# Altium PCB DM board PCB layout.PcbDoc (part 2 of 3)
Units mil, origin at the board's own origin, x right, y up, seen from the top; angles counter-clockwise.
Board outline 4444 x 6127 mil, 2 copper layers (Top Layer, Bottom Layer); 112 components, 94 nets, 2801 pads, 141 vias.
Unrouted connection lines stored in the file: 2.
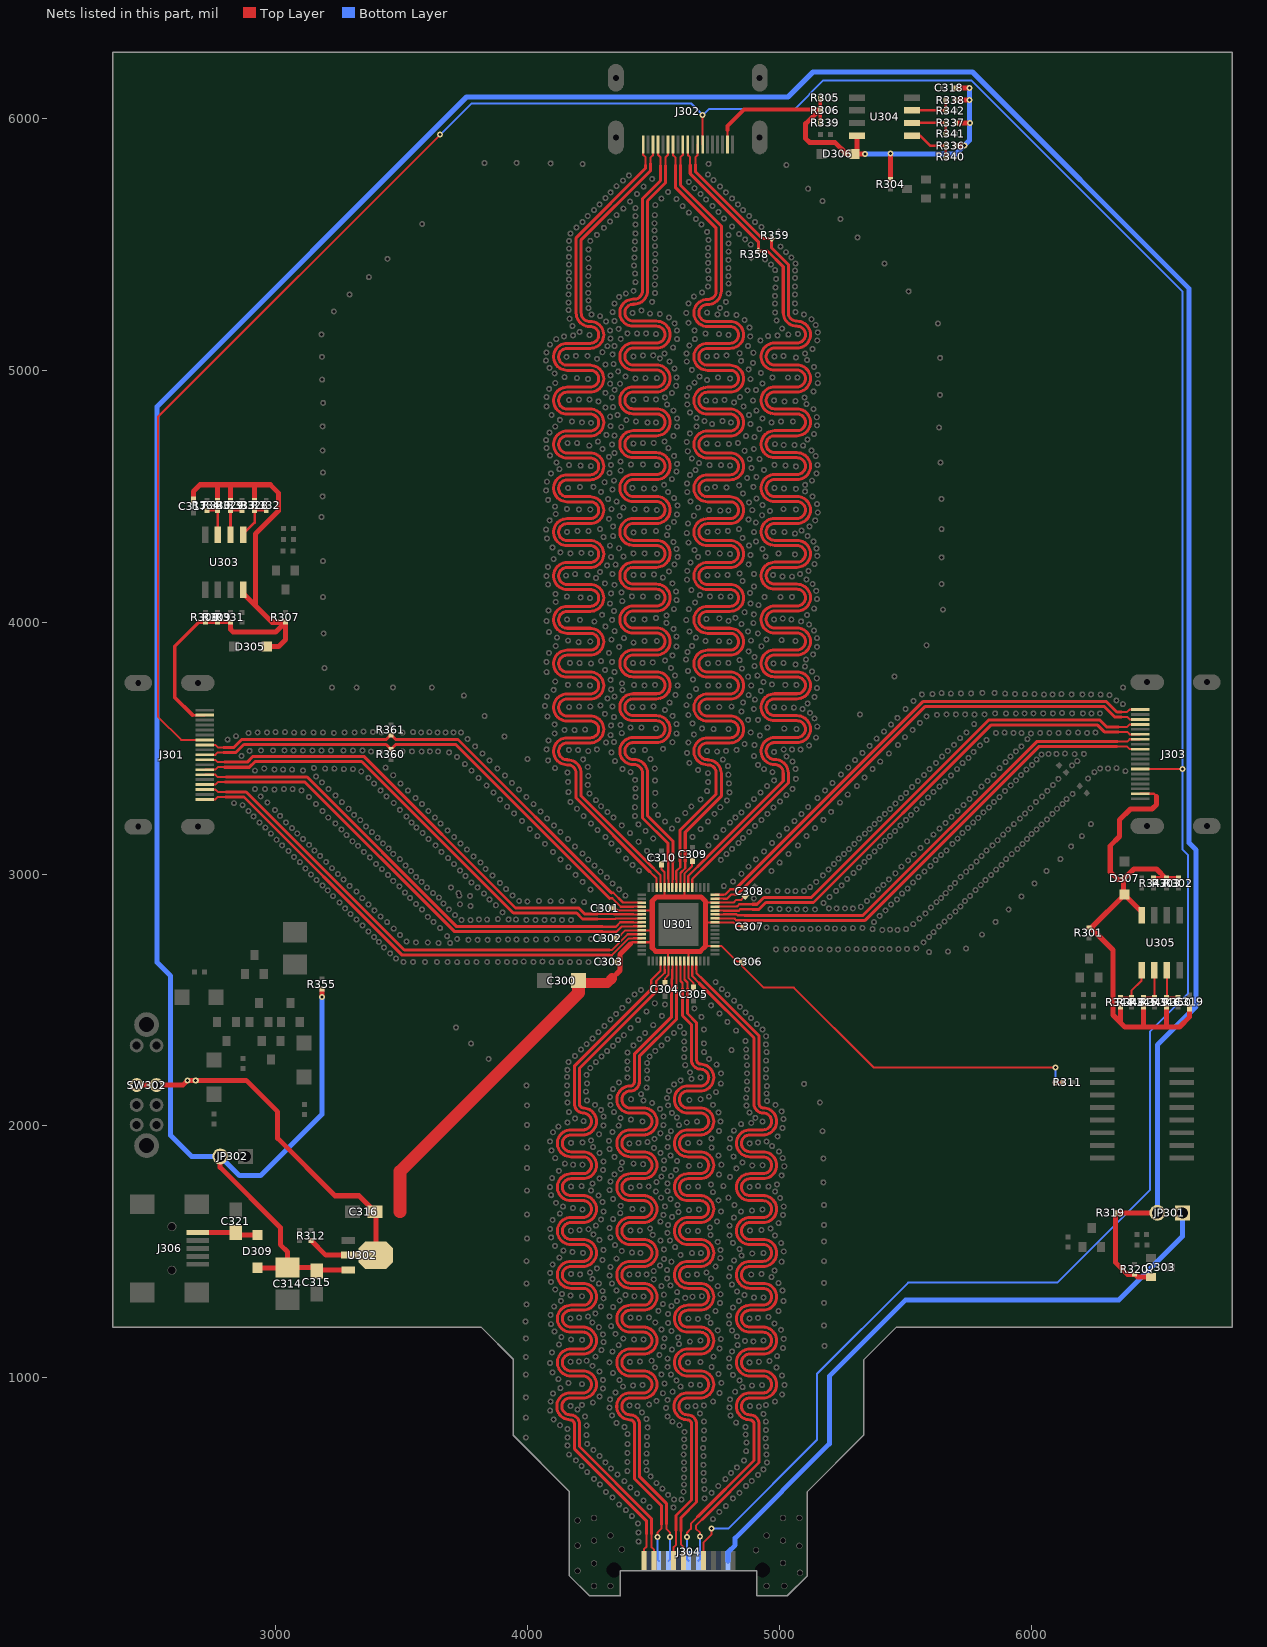
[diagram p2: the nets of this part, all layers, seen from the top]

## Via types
v1: diameter 24, hole 12, Top Layer to Bottom Layer, tented both sides, 141 vias

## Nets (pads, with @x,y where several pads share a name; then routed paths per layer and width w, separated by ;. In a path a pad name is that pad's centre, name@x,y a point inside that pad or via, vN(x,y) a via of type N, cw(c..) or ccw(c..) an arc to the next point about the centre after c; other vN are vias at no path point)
+3V3_3: C300.1 C301.1 C302.1 C303.1 C304.1 C305.1 C306.1 C307.1 C308.1 C309.1 C310.1 C316.2 R311.1 R312.2 SW302.2 SW302.6 U301.5 U301.10 U301.13 U301.22 U301.27 U301.35 U301.41 U301.46 U301.55 U301.60 U302.2 | length 6957.6
  Top Layer w7: 4544.88,2909.74 4544.88,3006
  Top Layer w8: C301.1@4335,2865 4350,2865 4359.88,2855.12 4491.87,2855.12 ; C302.1@4345,2745 4358,2745 4389.38,2776.38 4491.87,2776 ; C310.1@4533,3039 4533,3017.88 4544.88,3006 ; C304.1@4546,2570 4546,2585 4560.63,2599.63 4559,2693 ; 4623.62,2909.62 4623.62,3000.53 4653,3029.91 C309.1@4653,3053 ; 4639.37,2692.63 4639.37,2587.63 4659,2568 C305.1@4659,2548 ; C309.1@4653,3055 C309.1@4656,3058 ; 4707.39,2713.39 4771.61,2713.39 4833,2652 C306.1@4853,2652 ; 4707.39,2807.87 4817.13,2807.87 4831.59,2793.41 4854.59,2793.41 C307.1@4858,2790 ; 4707.39,2886.61 4818.61,2886.61 4829,2897 4850,2897 C308.1@4866.32,2913.32 ; C306.1@4853,2651 4853,2634 4938,2549 5058,2549 5375,2232 v1(6097,2232) ; v1(6097,2173) R311.1@6126.31,2173
  Top Layer w10: 4409,2722 4416.13,2729.13 U301.13@4454.33,2729.13 4495.16,2729.13
  Top Layer w20: SW302.6@2449.63,2162 2633,2162 v1(2652,2181) 2884,2181 3009,2056 3009,1951 3237,1723 3332,1723 3398.65,1656.35 U302.2@3398.65,1487 ; R312.2@3142,1545.32 3200.32,1487 U302.2@3298.21,1487 ; 4337.1,2586.1 4368,2617 4368,2681 4409,2722 ; C303.1@4349,2651 4368,2651 ; 4510,2907 4496,2893 4496,2707 4510,2693 4687,2693 4707.39,2713.39 4707.39,2891.61 4689.38,2909.62 4512.62,2909.62
  Top Layer w40: C300.1@4213.5,2567 4318,2567 4337.1,2586.1
  Top Layer w50: 3495,1659 3495,1820 4203.5,2528.5 C300.1@4203.5,2577
  Bottom Layer w8: v1(6097,2173) v1(6097,2232)
  Bottom Layer w20: v1(2652,2181) v1(2684,2181)
+5V_3: C314.1 C315.2 D309.2 JP301.2 JP302.2 Q303.2 R319.1 R320.2 R355.2 U302.3 | length 14380.5
  Top Layer w20: JP302.2@2781,1879 2781,1836 3020,1597 3020,1529 3049,1500 C314.1@3049,1438 ; D309.2@2930,1437 3048,1437 C314.1@3049,1438 ; v1(3185,2512) R355.2@3185,2543.32 ; U302.3@3289.37,1427.94 3168.94,1427.94 C315.2@3165,1424 3151,1438 C314.1@3049,1438 ; Q303.2@6476,1401 6421.31,1401 R320.2@6411,1411.32 6381.69,1411.32 6335.69,1457.32 R319.1@6335.69,1655 JP301.2@6501,1655
  Bottom Layer w20: v1(3185,2512) 3185,2046 2942,1803 2857,1803 JP302.2@2781,1879 2668,1879 2584,1963 2584,2596 2531,2649 2531,4856 3759,6084 5035,6084 5134,6183 5767,6183 6627,5323 6627,3123 6654,3096 6654,2474 6501,2321 JP301.2@6501,1655 JP301.2@6511,1655
+5V_A3: C317.1 D305.1 J301.18 R307.2 R308.1 R309.1 R328.1 R329.1 R330.1 R331.1 U303.8 | length 2328.9
  Top Layer w10: 2671.35,3630.65 J301.18@2720,3630.65
  Top Layer w15: 2671.35,3630.65 2601,3701 2601,3904 2696.32,3999.32 R331.1@2822,3999.32
  Top Layer w20: C317.1@2675,4485 2675,4519 2701,4545 2980,4545 3012,4513 3012,4441 2921.48,4350.48 2921.48,4065.11 ; R330.1@2770,4482.69 2770,4544 ; R331.1@2822,3999.32 2822,3971 2833,3960 3000.68,3960 R307.2@3040,3999.32 ; R329.1@2822,4482.69 2822,4545 ; U303.8@2872,4128.75 2872,4114 2986.68,3999.32 R307.2@3040,3999.32 ; R328.1@2918,4482.69 2918,4544 ; D305.1@2966,3903 3013,3903 3040,3930 R307.2@3040,3999.32
+5V_B3: C318.1 D306.1 J302.18 R304.2 R305.1 R306.1 R336.1 R337.1 R338.1 R339.1 U304.8 | length 1992.3
  Top Layer w9: J302.18@4794.65,5896 4794.65,5952
  Top Layer w15: 4794.65,5952 4794.65,5968.65 4860,6034 5162.31,6034 R306.1@5163.31,6033 ; R339.1@5163.31,5981 R305.1@5163.31,6081
  Top Layer w20: R306.1@5161,6034 5105,5978 5105,5919 5120,5904 5221,5904 5267,5858 v1(5341,5858) ; D306.1@5298,5858 5308.75,5868.75 U304.8@5308.75,5931 ; R304.2@5442,5757.69 v1(5442,5859) ; C318.1@5700,6120 v1(5755,6120) ; R336.1@5700.69,5891 v1(5735,5891) ; R337.1@5700.69,5981 v1(5757,5981) ; R338.1@5700.69,6072 v1(5756,6072)
  Bottom Layer w20: v1(5341,5858) 5701,5858 5755,5912 v1(5755,6120)
+5V_C3: C319.1 D307.1 J303.18 R301.2 R302.1 R303.1 R344.1 R345.1 R346.1 R347.1 U305.8 | length 2192
  Top Layer w9: J303.18@6433,3318.35 6487.65,3318.35 6498,3308
  Top Layer w15: R347.1@6485.31,2983.68 R302.1@6585,2983.68 ; 6552,2984.68 6553,2983.68
  Top Layer w20: R301.2@6229,2785.68 R301.2@6237.68,2785.68 ; 6354,2411 R344.1@6354,2471.32 ; D307.1@6371,2919 R301.2@6237.68,2785.68 ; U305.8@6442,2846.25 6370.13,2918.13 6366.63,2921.63 6366.63,2978.63 ; 6446,2396 R345.1@6446,2471.32 ; 6498,3308 6498,3276 6480,3258 6394,3258 6351,3215 6351,3149 6314,3112 6314,3008 6343.37,2978.63 6366.63,2978.63 ; R303.1@6534,2983.68 6497.69,3020 6408,3020 6366.63,2978.63 ; 6538,2393 R346.1@6538,2471.32 ; C319.1@6629,2467 6629,2433 6589,2393 6372,2393 6325,2440 6325,2698.37 R301.2@6237.68,2785.68
+5V_D3: J304.18 JP301.1 | length 2624.2
  Bottom Layer w20: J304.18@4797.48,274 4797.48,308.48 4825,336 4825,364 5199,738 5199,1007 5502,1310 6349,1310 6601,1562 JP301.1@6601,1655
+5V_JACK_3: 
+5V_USB_3: C321.1 D309.1 J306.1 | length 242.1
  Top Layer w20: J306.1@2692.06,1576.99 C321.1@2843,1577 2852.98,1567 D309.1@2930,1567
A0_A3: R328.2 R332.1 U303.1 | length 161.1
  Top Layer w10: U303.1@2872,4347.25 2872,4349 2918,4395 R328.2@2918,4443.31 R332.1@2964,4443.32
A0_B3: R336.2 R340.1 U304.1 | length 194.6
  Top Layer w10: U304.1@5527.25,5931 5559,5931 5599,5891 R336.2@5661.31,5891 R340.1@5661.31,5847
A0_C3: R344.2 R348.1 U305.1 | length 176.9
  Top Layer w8: R344.2@6354,2510.68 R348.1@6398,2510.68 6398,2537 6438,2577 U305.1@6438,2627
A1_A3: R329.2 R333.1 U303.2 | length 141.1
  Top Layer w10: U303.2@2822,4347.25 R329.2@2822,4443.31 R333.1@2867,4443.31
A1_B3: R337.2 R341.1 U304.2 | length 177.1
  Top Layer w10: U304.2@5527.25,5981 R337.2@5661.31,5981 R341.1@5661.31,5938
A1_C3: R345.2 R349.1 U305.2 | length 149.5
  Top Layer w8: R345.2@6446,2510.68 6488,2510.68 6489,2511.68 U305.2@6489,2617.75
A2_A3: R330.2 R334.1 U303.3 | length 138.9
  Top Layer w10: R334.1@2728,4443.31 R330.2@2770,4443.31 2772,4441.31 U303.3@2772,4347.25
A2_B3: R338.2 R342.1 U304.3 | length 174.5
  Top Layer w10: U304.3@5527.25,6031 5660.31,6031 5661.31,6032 R338.2@5661.31,6072
A2_C3: R346.2 R350.1 U305.3 | length 149.5
  Top Layer w8: U305.3@6539,2617.75 6539,2511.68 6540,2510.68 R350.1@6582,2510.68
CEC_D3: J301.13 J302.13 J303.13 J304.13 | length 12936.1
  Top Layer w8: J301.13@2720,3532.22 2625.78,3532.22 2535,3623 2535,4816 v1(3653.77,5934.77) ; J302.13@4696.22,5896 v1(4696.22,6012.78) ; J304.13@4699.06,274 4699.06,346.06 4732,379 v1(4732,402) ; J303.13@6433,3416.78 v1@6600,3416.78
  Bottom Layer w8: v1@3654.27,5934.27 3779,6059 4650,6059 v1(4696.22,6012.78) ; v1@4690.05,6018.95 4703.95,6018.95 4721,6036 5061,6036 5175,6150 5763,6150 6600,5313 6600,3098 6623,3075 6623,2526 6471,2374 6471,1745 6104,1378 5512,1378 5150,1016 5150,754 4798,402 v1(4732,402)
  other v1: 6600,3416
D0+: J304.7 U301.25 | length 3996.1
  Top Layer w8: J304.7@4580.94,280 4580.94,328.37 4590.63,338.06 4590.63,395
  Top Layer w9: U301.25@4607.87,2654.33 4607.87,2575.13 4616,2567 4616,2545
  Top Layer w12: J304.7@4580.94,274 J304.7@4580.94,280 ; 4590.63,395 4590.63,453.91 4652,515.28 4652,817 ccw(c4635.5,817) 4635.5,833.5 cw(c4635.5,887) 4582,887 cw(c4635.5,887) 4635.5,940.5 4686.77,940.5 ccw(c4686.77,974) 4720.27,974 ccw(c4686.77,974) 4686.77,1007.5 4637.23,1007.5 cw(c4637.23,1061) 4583.73,1061 cw(c4637.23,1061) 4637.23,1114.5 4686.77,1114.5 ccw(c4686.77,1148) 4720.27,1148 ccw(c4686.77,1148) 4686.77,1181.5 4637.23,1181.5 cw(c4637.23,1235) 4583.73,1235 cw(c4637.23,1235) 4637.23,1288.5 4686.77,1288.5 ccw(c4686.77,1322) 4720.27,1322 ccw(c4686.77,1322) 4686.77,1355.5 4637.23,1355.5 cw(c4637.23,1409) 4583.73,1409 cw(c4637.23,1409) 4637.23,1462.5 4686.77,1462.5 ccw(c4686.77,1496) 4720.27,1496 ccw(c4686.77,1496) 4686.77,1529.5 4637.23,1529.5 cw(c4637.23,1583) 4583.73,1583 cw(c4637.23,1583) 4637.23,1636.5 4686.77,1636.5 ccw(c4686.77,1670) 4720.27,1670 ccw(c4686.77,1670) 4686.77,1703.5 4637.23,1703.5 cw(c4637.23,1757) 4583.73,1757 cw(c4637.23,1757) 4637.23,1810.5 4686.77,1810.5 ccw(c4686.77,1844) 4720.27,1844 ccw(c4686.77,1844) 4686.77,1877.5 4637.23,1877.5 cw(c4637.23,1931) 4583.73,1931 cw(c4637.23,1931) 4637.23,1984.5 4686.77,1984.5 ccw(c4686.77,2018) 4720.27,2018 ccw(c4686.77,2018) 4686.77,2051.5 4637.23,2051.5 cw(c4637.23,2105) 4583.73,2105 cw(c4637.23,2105) 4637.23,2158.5 4686.77,2158.5 ccw(c4686.77,2192) 4720.27,2192 ccw(c4686.77,2192) 4686.77,2225.5 cw(c4686.77,2235.5) 4684.89,2225.68 cw(c4688.5,2262) 4652,2262 4652,2401.72 4616,2437.72 4616,2545
D0-: J304.9 U301.26 | length 3997.8
  Top Layer w8: 4610.63,392 4610.63,338.06 4620.31,328.37 J304.9@4620.31,290
  Top Layer w9: U301.26@4623.62,2654.33 4623.62,2581.65 4636,2569.27 4636,2545
  Top Layer w12: 4610.63,392 4610.63,445.63 4672,507 4672,817 ccw(c4635.5,817) 4635.5,853.5 cw(c4635.5,887) 4602,887 cw(c4635.5,887) 4635.5,920.5 4686.77,920.5 ccw(c4686.77,974) 4740.27,974 ccw(c4686.77,974) 4686.77,1027.5 4637.23,1027.5 cw(c4637.23,1061) 4603.73,1061 cw(c4637.23,1061) 4637.23,1094.5 4686.77,1094.5 ccw(c4686.77,1148) 4740.27,1148 ccw(c4686.77,1148) 4686.77,1201.5 4637.23,1201.5 cw(c4637.23,1235) 4603.73,1235 cw(c4637.23,1235) 4637.23,1268.5 4686.77,1268.5 ccw(c4686.77,1322) 4740.27,1322 ccw(c4686.77,1322) 4686.77,1375.5 4637.23,1375.5 cw(c4637.23,1409) 4603.73,1409 cw(c4637.23,1409) 4637.23,1442.5 4686.77,1442.5 ccw(c4686.77,1496) 4740.27,1496 ccw(c4686.77,1496) 4686.77,1549.5 4637.23,1549.5 cw(c4637.23,1583) 4603.73,1583 cw(c4637.23,1583) 4637.23,1616.5 4686.77,1616.5 ccw(c4686.77,1670) 4740.27,1670 ccw(c4686.77,1670) 4686.77,1723.5 4637.23,1723.5 cw(c4637.23,1757) 4603.73,1757 cw(c4637.23,1757) 4637.23,1790.5 4686.77,1790.5 ccw(c4686.77,1844) 4740.27,1844 ccw(c4686.77,1844) 4686.77,1897.5 4637.23,1897.5 cw(c4637.23,1931) 4603.73,1931 cw(c4637.23,1931) 4637.23,1964.5 4686.77,1964.5 ccw(c4686.77,2018) 4740.27,2018 ccw(c4686.77,2018) 4686.77,2071.5 4637.23,2071.5 cw(c4637.23,2105) 4603.73,2105 cw(c4637.23,2105) 4637.23,2138.5 4686.77,2138.5 ccw(c4686.77,2192) 4740.27,2192 ccw(c4686.77,2192) 4689.81,2245.41 ccw(c4688.5,2235.5) 4688.5,2245.5 cw(c4688.5,2262) 4672,2262 4672,2410 4636,2446 4636,2545 ; J304.9@4620.31,274 J304.9@4620.31,290
D1+: J304.4 U301.23 | length 4004.9
  Top Layer w8: v1(4516,368) 4516,386 4532,402 4532,419
  Top Layer w9: 4573,2550 4573,2582 4575.75,2584.75 4575.75,2620.99 4576.38,2621.61 U301.23@4576.38,2654.33
  Top Layer w12: 4408.27,2158.5 ccw(c4408.8,2105) 4408.8,2051.5 4461.2,2051.5 cw(c4461.2,2018) 4494.7,2018 cw(c4461.2,2018) 4461.2,1984.5 4408.8,1984.5 ccw(c4408.8,1931) 4408.8,1877.5 4461.2,1877.5 cw(c4461.2,1844) 4494.7,1844 cw(c4461.2,1844) 4461.2,1810.5 4408.8,1810.5 ccw(c4408.8,1757) 4408.8,1703.5 4461.2,1703.5 cw(c4461.2,1670) 4494.7,1670 cw(c4461.2,1670) 4461.2,1636.5 4408.8,1636.5 ccw(c4408.8,1583) 4408.8,1529.5 4461.2,1529.5 cw(c4461.2,1496) 4494.7,1496 cw(c4461.2,1496) 4461.2,1462.5 4408.8,1462.5 ccw(c4408.8,1409) 4408.8,1355.5 4461.2,1355.5 cw(c4461.2,1322) 4494.7,1322 cw(c4461.2,1322) 4461.2,1288.5 4408.8,1288.5 ccw(c4408.8,1235) 4408.8,1181.5 4461.2,1181.5 cw(c4461.2,1148) 4494.7,1148 cw(c4461.2,1148) 4461.2,1114.5 4408.8,1114.5 ccw(c4408.8,1061) 4408.8,1007.5 4461.2,1007.5 cw(c4461.2,974) 4494.7,974 cw(c4461.2,974) 4461.2,940.5 4408.5,940.5 ccw(c4408.5,887) 4408.5,833.5 cw(c4408.5,817) 4425,817 4425,600.72 4532,493.72 4532,457.72 4532,419 ; 4408.5,2158.5 ccw(c4408.5,2175) 4425,2175 4425,2285 4573,2433 4573,2550
  Bottom Layer w8: v1(4516,368) 4516,279.89 J304.4@4521.89,274
D01+: J301.7 U301.7 | length 2007.9
  Top Layer w8: J301.7@2720,3414.11 2762,3414.11 2771.68,3423.8 2798.8,3423.8
  Top Layer w9: 4279,2821.5 4334.5,2821.5 4349.5,2821.5 4351,2823 4420.99,2823 4421.61,2823.62 U301.7@4454.33,2823.62
  Top Layer w12: 2798.8,3423.8 2896.8,3423.8 2920,3447 3342.71,3447 3365.92,3423.8 3944.72,2845 4196,2845 4219.5,2821.5 4279,2821.5
D1-: J304.6 U301.24 | length 4002.5
  Top Layer w8: 4552,420 4552,401 4566,387 v1(4566,369)
  Top Layer w9: U301.24@4592.13,2654.33 4592.13,2621.61 4592.75,2620.99 4592.75,2550
  Top Layer w12: 4408.54,2138.5 ccw(c4408.8,2105) 4408.8,2071.5 4461.2,2071.5 cw(c4461.2,2018) 4514.7,2018 cw(c4461.2,2018) 4461.2,1964.5 4408.8,1964.5 ccw(c4408.8,1931) 4408.8,1897.5 4461.2,1897.5 cw(c4461.2,1844) 4514.7,1844 cw(c4461.2,1844) 4461.2,1790.5 4408.8,1790.5 ccw(c4408.8,1757) 4408.8,1723.5 4461.2,1723.5 cw(c4461.2,1670) 4514.7,1670 cw(c4461.2,1670) 4461.2,1616.5 4408.8,1616.5 ccw(c4408.8,1583) 4408.8,1549.5 4461.2,1549.5 cw(c4461.2,1496) 4514.7,1496 cw(c4461.2,1496) 4461.2,1442.5 4408.8,1442.5 ccw(c4408.8,1409) 4408.8,1375.5 4461.2,1375.5 cw(c4461.2,1322) 4514.7,1322 cw(c4461.2,1322) 4461.2,1268.5 4408.8,1268.5 ccw(c4408.8,1235) 4408.8,1201.5 4461.2,1201.5 cw(c4461.2,1148) 4514.7,1148 cw(c4461.2,1148) 4461.2,1094.5 4408.8,1094.5 ccw(c4408.8,1061) 4408.8,1027.5 4461.2,1027.5 cw(c4461.2,974) 4514.7,974 cw(c4461.2,974) 4461.2,920.5 4408.5,920.5 ccw(c4408.5,887) 4408.5,853.5 cw(c4408.5,817) 4445,817 4445,609 4552,502 4552,436 4552,420 ; 4409.13,2138.51 ccw(c4408.5,2175) 4445,2175 4445,2276.72 4593,2424.72 4593,2550
  Bottom Layer w8: J304.6@4561.26,274 4567,279.74 v1@4567,369
D01-: J301.9 U301.6 | length 2003.8
  Top Layer w8: J301.9@2720,3453.48 2762,3453.48 2771.68,3443.8 2796.8,3443.8
  Top Layer w9: 4279,2841.5 4342.5,2841.5 ; 4344,2840 4420.99,2840 4421.61,2839.37 U301.6@4454.33,2839.37
  Top Layer w12: 2798.8,3443.8 2888.51,3443.8 2911.72,3467 3351,3467 3374.2,3443.8 3953,2865 4204.28,2865 4227.79,2841.5 4279,2841.5
D2+: J304.1 U301.20 | length 3996.5
  Top Layer w8: J304.1@4462.83,274 4462.83,319 4472.52,328.68 4472.52,380
  Top Layer w9: 4492,2556 4492,2579.04 4528.51,2615.55 4528.51,2620.99 4529.13,2621.61 U301.20@4529.13,2654.33
  Top Layer w12: 4472.52,380 4472.52,433.48 4187,719 4187,817 ccw(c4170.5,817) 4170.5,833.5 cw(c4170.5,887) 4170.5,940.5 4221.1,940.5 ccw(c4221.1,974) 4254.6,974 ccw(c4221.1,974) 4221.1,1007.5 4172.9,1007.5 cw(c4172.9,1061) 4172.9,1114.5 4221.1,1114.5 ccw(c4221.1,1148) 4254.6,1148 ccw(c4221.1,1148) 4221.1,1181.5 4172.9,1181.5 cw(c4172.9,1235) 4172.9,1288.5 4221.1,1288.5 ccw(c4221.1,1322) 4254.6,1322 ccw(c4221.1,1322) 4221.1,1355.5 4172.9,1355.5 cw(c4172.9,1409) 4172.9,1462.5 4221.1,1462.5 ccw(c4221.1,1496) 4254.6,1496 ccw(c4221.1,1496) 4221.1,1529.5 4172.9,1529.5 cw(c4172.9,1583) 4172.9,1636.5 4221.1,1636.5 ccw(c4221.1,1670) 4254.6,1670 ccw(c4221.1,1670) 4221.1,1703.5 4172.9,1703.5 cw(c4172.9,1757) 4172.9,1810.5 4221.1,1810.5 ccw(c4221.1,1844) 4254.6,1844 ccw(c4221.1,1844) 4221.1,1877.5 4172.9,1877.5 cw(c4172.9,1931) 4172.9,1984.5 4221.1,1984.5 ccw(c4221.1,2018) 4254.6,2018 ccw(c4221.1,2018) 4221.1,2051.5 cw(c4221.1,2061.5) 4218.5,2051.85 cw(c4223.5,2088) 4187,2088 4187,2237.28 4492,2542.28 4492,2556
D02+: J302.7 U301.57 | length 5999.4
  Top Layer w8: J302.7@4578.11,5896 4578.11,5854 4587.8,5844.32 4587.8,5815
  Top Layer w9: U301.57@4592.13,2945.67 4592.13,2978.39 4591.5,2979.01 4591.5,3008.02 4591.5,3011.54 4607,3027.04 4607,3050
  Top Layer w12: 4587.8,5815 4587.8,5725.92 4750,5563.72 4750,5314 cw(c4716.5,5314) 4716.5,5280.5 4714.61,5280.5 ccw(c4714.61,5227) 4714.61,5173.5 4805.39,5173.5 cw(c4805.39,5140) 4838.89,5140 cw(c4805.39,5140) 4805.39,5106.5 4714.61,5106.5 ccw(c4714.61,5053) 4714.61,4999.5 4805.39,4999.5 cw(c4805.39,4966) 4838.89,4966 cw(c4805.39,4966) 4805.39,4932.5 4714.61,4932.5 ccw(c4714.61,4879) 4714.61,4825.5 4805.39,4825.5 cw(c4805.39,4792) 4838.89,4792 cw(c4805.39,4792) 4805.39,4758.5 4714.61,4758.5 ccw(c4714.61,4705) 4714.61,4651.5 4805.39,4651.5 cw(c4805.39,4618) 4838.89,4618 cw(c4805.39,4618) 4805.39,4584.5 4714.61,4584.5 ccw(c4714.61,4531) 4714.61,4477.5 4805.39,4477.5 cw(c4805.39,4444) 4838.89,4444 cw(c4805.39,4444) 4805.39,4410.5 4714.61,4410.5 ccw(c4714.61,4357) 4714.61,4303.5 4805.39,4303.5 cw(c4805.39,4270) 4838.89,4270 cw(c4805.39,4270) 4805.39,4236.5 4714.61,4236.5 ccw(c4714.61,4183) 4714.61,4129.5 4805.39,4129.5 cw(c4805.39,4096) 4838.89,4096 cw(c4805.39,4096) 4805.39,4062.5 4714.61,4062.5 ccw(c4714.61,4009) 4714.61,3955.5 4805.39,3955.5 cw(c4805.39,3922) 4838.89,3922 cw(c4805.39,3922) 4805.39,3888.5 4714.61,3888.5 ccw(c4714.61,3835) 4714.61,3781.5 4805.39,3781.5 cw(c4805.39,3748) 4838.89,3748 cw(c4805.39,3748) 4805.39,3714.5 4714.61,3714.5 ccw(c4714.61,3661) 4714.61,3607.5 4805.39,3607.5 cw(c4805.39,3574) 4838.89,3574 cw(c4805.39,3574) 4805.39,3540.5 4714.61,3540.5 ccw(c4714.61,3487) 4714.61,3433.5 4716.5,3433.5 cw(c4716.5,3400) 4750,3400 4750,3317.28 4607,3174.28 4607,3050
D2-: J304.3 U301.21 | length 3995.2
  Top Layer w8: 4492.52,380 4492.52,328.69 4502.2,319 J304.3@4502.2,274
  Top Layer w9: 4512,2556 4512,2575 4545.51,2608.51 4545.51,2620.99 4544.88,2621.61 U301.21@4544.88,2654.33
  Top Layer w12: 4492.52,380 4492.52,441.76 4207,727.28 4207,817 ccw(c4170.5,817) 4170.5,853.5 cw(c4170.5,887) 4170.5,920.5 4221.1,920.5 ccw(c4221.1,974) 4274.6,974 ccw(c4221.1,974) 4221.1,1027.5 4172.9,1027.5 cw(c4172.9,1061) 4172.9,1094.5 4221.1,1094.5 ccw(c4221.1,1148) 4274.6,1148 ccw(c4221.1,1148) 4221.1,1201.5 4172.9,1201.5 cw(c4172.9,1235) 4172.9,1268.5 4221.1,1268.5 ccw(c4221.1,1322) 4274.6,1322 ccw(c4221.1,1322) 4221.1,1375.5 4172.9,1375.5 cw(c4172.9,1409) 4172.9,1442.5 4221.1,1442.5 ccw(c4221.1,1496) 4274.6,1496 ccw(c4221.1,1496) 4221.1,1549.5 4172.9,1549.5 cw(c4172.9,1583) 4172.9,1616.5 4221.1,1616.5 ccw(c4221.1,1670) 4274.6,1670 ccw(c4221.1,1670) 4221.1,1723.5 4172.9,1723.5 cw(c4172.9,1757) 4172.9,1790.5 4221.1,1790.5 ccw(c4221.1,1844) 4274.6,1844 ccw(c4221.1,1844) 4221.1,1897.5 4172.9,1897.5 cw(c4172.9,1931) 4172.9,1964.5 4221.1,1964.5 ccw(c4221.1,2018) 4274.6,2018 ccw(c4221.1,2018) 4225.32,2071.34 ccw(c4223.5,2061.5) 4223.5,2071.5 cw(c4223.5,2088) 4207,2088 4207,2229 4512,2534 4512,2556
D02-: J302.9 U301.56 | length 6000.6
  Top Layer w8: 4607.8,5815 4607.8,5844.31 4617.48,5854 J302.9@4617.48,5896
  Top Layer w9: U301.56@4607.87,2945.67 4607.87,2978.39 4608.5,2979.01 4608.5,3004.5 4627,3023 4627,3050
  Top Layer w12: 4607.8,5815 4607.8,5734.2 4770,5572 4770,5314 cw(c4716.5,5314) 4716.5,5260.5 4714.61,5260.5 ccw(c4714.61,5227) 4714.61,5193.5 4805.39,5193.5 cw(c4805.39,5140) 4858.89,5140 cw(c4805.39,5140) 4805.39,5086.5 4714.61,5086.5 ccw(c4714.61,5053) 4714.61,5019.5 4805.39,5019.5 cw(c4805.39,4966) 4858.89,4966 cw(c4805.39,4966) 4805.39,4912.5 4714.61,4912.5 ccw(c4714.61,4879) 4714.61,4845.5 4805.39,4845.5 cw(c4805.39,4792) 4858.89,4792 cw(c4805.39,4792) 4805.39,4738.5 4714.61,4738.5 ccw(c4714.61,4705) 4714.61,4671.5 4805.39,4671.5 cw(c4805.39,4618) 4858.89,4618 cw(c4805.39,4618) 4805.39,4564.5 4714.61,4564.5 ccw(c4714.61,4531) 4714.61,4497.5 4805.39,4497.5 cw(c4805.39,4444) 4858.89,4444 cw(c4805.39,4444) 4805.39,4390.5 4714.61,4390.5 ccw(c4714.61,4357) 4714.61,4323.5 4805.39,4323.5 cw(c4805.39,4270) 4858.89,4270 cw(c4805.39,4270) 4805.39,4216.5 4714.61,4216.5 ccw(c4714.61,4183) 4714.61,4149.5 4805.39,4149.5 cw(c4805.39,4096) 4858.89,4096 cw(c4805.39,4096) 4805.39,4042.5 4714.61,4042.5 ccw(c4714.61,4009) 4714.61,3975.5 4805.39,3975.5 cw(c4805.39,3922) 4858.89,3922 cw(c4805.39,3922) 4805.39,3868.5 4714.61,3868.5 ccw(c4714.61,3835) 4714.61,3801.5 4805.39,3801.5 cw(c4805.39,3748) 4858.89,3748 cw(c4805.39,3748) 4805.39,3694.5 4714.61,3694.5 ccw(c4714.61,3661) 4714.61,3627.5 4805.39,3627.5 cw(c4805.39,3574) 4858.89,3574 cw(c4805.39,3574) 4805.39,3520.5 4714.61,3520.5 ccw(c4714.61,3487) 4714.61,3453.5 4716.5,3453.5 cw(c4716.5,3400) 4770,3400 4770,3309 4627,3166 4627,3050
D3+: J304.12 U301.29 | length 4006.6
  Top Layer w8: v1(4686,370) 4686,385 4669,402 4669,413 4694.11,438.11
  Top Layer w9: U301.29@4670.87,2654.33 4670.87,2621.61 4671.49,2620.99 4671.49,2606.51 4697,2581
  Top Layer w12: 4694.11,438.11 4920,664 4920,817 ccw(c4883.5,817) 4883.5,853.5 cw(c4883.5,887) 4850,887 cw(c4883.5,887) 4883.5,920.5 4936.31,920.5 ccw(c4936.31,974) 4989.81,974 ccw(c4936.31,974) 4936.31,1027.5 4883.69,1027.5 cw(c4883.69,1061) 4850.19,1061 cw(c4883.69,1061) 4883.69,1094.5 4936.31,1094.5 ccw(c4936.31,1148) 4989.81,1148 ccw(c4936.31,1148) 4936.31,1201.5 4883.69,1201.5 cw(c4883.69,1235) 4850.19,1235 cw(c4883.69,1235) 4883.69,1268.5 4936.31,1268.5 ccw(c4936.31,1322) 4989.81,1322 ccw(c4936.31,1322) 4936.31,1375.5 4883.69,1375.5 cw(c4883.69,1409) 4850.19,1409 cw(c4883.69,1409) 4883.69,1442.5 4936.31,1442.5 ccw(c4936.31,1496) 4989.81,1496 ccw(c4936.31,1496) 4936.31,1549.5 4883.69,1549.5 cw(c4883.69,1583) 4850.19,1583 cw(c4883.69,1583) 4883.69,1616.5 4936.31,1616.5 ccw(c4936.31,1670) 4989.81,1670 ccw(c4936.31,1670) 4936.31,1723.5 4883.69,1723.5 cw(c4883.69,1757) 4850.19,1757 cw(c4883.69,1757) 4883.69,1790.5 4936.31,1790.5 ccw(c4936.31,1844) 4989.81,1844 ccw(c4936.31,1844) 4936.31,1897.5 4883.69,1897.5 cw(c4883.69,1931) 4850.19,1931 cw(c4883.69,1931) 4883.69,1964.5 4936.31,1964.5 ccw(c4936.31,2018) 4989.81,2018 ccw(c4936.31,2018) 4936.6,2071.5 ; 4697,2581 4920,2358 4920,2088 ccw(c4936.5,2088) 4936.47,2071.5
  Bottom Layer w8: J304.12@4679.37,274 4686,280.63 v1(4686,370)
D03+: J303.7 U301.43 | length 1978.7
  Top Layer w8: 6342,3525.2 6381.32,3525.2 6391,3534.89 J303.7@6433,3534.89
  Top Layer w9: U301.43@4745.67,2839.37 4778.39,2839.37 4779.01,2840 4802.48,2840 4830,2840 4834,2836 4862,2836
  Top Layer w12: 4862,2836 5332.72,2836 6021.92,3525.2 6342,3525.2
D3-: J304.10 U301.28 | length 4004.3
  Top Layer w8: v1(4634,368) 4634,386 4649,401 4649,421.28 4676.59,448.88
  Top Layer w9: U301.28@4655.12,2654.33 4655.12,2621.61 4654.49,2620.99 4654.49,2595.22 4682.86,2566.86
  Top Layer w12: 4676.59,448.88 4900,672.28 4900,817 ccw(c4883.5,817) 4883.5,833.5 cw(c4883.5,887) 4830,887 cw(c4883.5,887) 4883.5,940.5 4936.31,940.5 ccw(c4936.31,974) 4969.81,974 ccw(c4936.31,974) 4936.31,1007.5 4883.69,1007.5 cw(c4883.69,1061) 4830.19,1061 cw(c4883.69,1061) 4883.69,1114.5 4936.31,1114.5 ccw(c4936.31,1148) 4969.81,1148 ccw(c4936.31,1148) 4936.31,1181.5 4883.69,1181.5 cw(c4883.69,1235) 4830.19,1235 cw(c4883.69,1235) 4883.69,1288.5 4936.31,1288.5 ccw(c4936.31,1322) 4969.81,1322 ccw(c4936.31,1322) 4936.31,1355.5 4883.69,1355.5 cw(c4883.69,1409) 4830.19,1409 cw(c4883.69,1409) 4883.69,1462.5 4936.31,1462.5 ccw(c4936.31,1496) 4969.81,1496 ccw(c4936.31,1496) 4936.31,1529.5 4883.69,1529.5 cw(c4883.69,1583) 4830.19,1583 cw(c4883.69,1583) 4883.69,1636.5 4936.31,1636.5 ccw(c4936.31,1670) 4969.81,1670 ccw(c4936.31,1670) 4936.31,1703.5 4883.69,1703.5 cw(c4883.69,1757) 4830.19,1757 cw(c4883.69,1757) 4883.69,1810.5 4936.31,1810.5 ccw(c4936.31,1844) 4969.81,1844 ccw(c4936.31,1844) 4936.31,1877.5 4883.69,1877.5 cw(c4883.69,1931) 4830.19,1931 cw(c4883.69,1931) 4883.69,1984.5 4936.31,1984.5 ccw(c4936.31,2018) 4969.81,2018 ccw(c4936.31,2018) 4936.33,2051.5 ; 4682.86,2566.86 4900,2349.72 4900,2088 ccw(c4936.5,2088) 4936.15,2051.5
  Bottom Layer w8: v1(4634,368) 4634,280 J304.10@4640,274
D03-: J303.9 U301.42 | length 1980
  Top Layer w8: 6341,3505.2 6381.31,3505.2 6391,3495.52 J303.9@6433,3495.52
  Top Layer w9: U301.42@4745.67,2823.62 4778.39,2823.62 4779.01,2823 4822.96,2823 4829.96,2816 4862,2816
  Top Layer w12: 4862,2816 5341,2816 6030.2,3505.2 6341,3505.2
D11+: J301.4 U301.9 | length 1993
  Top Layer w8: J301.4@2720,3355.06 2762,3355.06 2771.68,3364.74 2801,3364.74
  Top Layer w9: 4299,2771 4354.54,2771 4375.04,2791.5 4420.99,2791.5 4421.61,2792.13 U301.9@4454.33,2792.13
  Top Layer w12: 2801,3364.74 3117.97,3364.74 3711.72,2771 4299,2771
D11-: J301.6 U301.8 | length 1991.8
  Top Layer w8: J301.6@2720,3394.43 2762,3394.43 2771.68,3384.74 2804,3384.74
  Top Layer w9: 4299,2791 4352,2791 4369.5,2808.5 4396.02,2808.5 4420.99,2808.5 4421.61,2807.87 U301.8@4454.33,2807.87
  Top Layer w12: 2804,3384.74 3126.26,3384.74 3720,2791 4299,2791
D12+: J302.4 U301.59 | length 5984.9
  Top Layer w8: J302.4@4519.06,5896 4519.06,5854 4528.74,5844.32 4528.74,5813
  Top Layer w9: 4560,3048 4560,2981.01 4560.63,2978.39 U301.59@4560.63,2945.67
  Top Layer w12: 4528.74,5813 4528.74,5752.03 4457,5680.28 4457,5315 cw(c4423.5,5315) 4423.5,5281.5 4420.5,5281.5 ccw(c4420.5,5228) 4420.5,5174.5 4513.5,5174.5 cw(c4513.5,5141) 4547,5141 cw(c4513.5,5141) 4513.5,5107.5 4420.5,5107.5 ccw(c4420.5,5054) 4420.5,5000.5 4513.5,5000.5 cw(c4513.5,4967) 4547,4967 cw(c4513.5,4967) 4513.5,4933.5 4420.5,4933.5 ccw(c4420.5,4880) 4420.5,4826.5 4513.5,4826.5 cw(c4513.5,4793) 4547,4793 cw(c4513.5,4793) 4513.5,4759.5 4420.5,4759.5 ccw(c4420.5,4706) 4420.5,4652.5 4513.5,4652.5 cw(c4513.5,4619) 4547,4619 cw(c4513.5,4619) 4513.5,4585.5 4420.5,4585.5 ccw(c4420.5,4532) 4420.5,4478.5 4513.5,4478.5 cw(c4513.5,4445) 4547,4445 cw(c4513.5,4445) 4513.5,4411.5 4420.5,4411.5 ccw(c4420.5,4358) 4420.5,4304.5 4513.5,4304.5 cw(c4513.5,4271) 4547,4271 cw(c4513.5,4271) 4513.5,4237.5 4420.5,4237.5 ccw(c4420.5,4184) 4420.5,4130.5 4513.5,4130.5 cw(c4513.5,4097) 4547,4097 cw(c4513.5,4097) 4513.5,4063.5 4420.5,4063.5 ccw(c4420.5,4010) 4420.5,3956.5 4513.5,3956.5 cw(c4513.5,3923) 4547,3923 cw(c4513.5,3923) 4513.5,3889.5 4420.5,3889.5 ccw(c4420.5,3836) 4420.5,3782.5 4513.5,3782.5 cw(c4513.5,3749) 4547,3749 cw(c4513.5,3749) 4513.5,3715.5 4420.5,3715.5 ccw(c4420.5,3662) 4420.5,3608.5 4513.5,3608.5 cw(c4513.5,3575) 4547,3575 cw(c4513.5,3575) 4513.5,3541.5 4420.5,3541.5 ccw(c4420.5,3488) 4420.5,3434.5 4423.5,3434.5 cw(c4423.5,3401) 4457,3401 4457,3222.72 4559,3120.72 4559,3048
D12-: J302.6 U301.58 | length 5983.1
  Top Layer w8: 4548.74,5813 4548.74,5844.32 4558.43,5854 J302.6@4558.43,5896
  Top Layer w9: U301.58@4576.38,2945.67 4576.38,2978.39 4577,2979.01 4577,3046
  Top Layer w12: 4548.74,5813 4548.74,5743.74 4477,5672 4477,5315 cw(c4423.5,5315) 4423.5,5261.5 4420.5,5261.5 ccw(c4420.5,5228) 4420.5,5194.5 4513.5,5194.5 cw(c4513.5,5141) 4567,5141 cw(c4513.5,5141) 4513.5,5087.5 4420.5,5087.5 ccw(c4420.5,5054) 4420.5,5020.5 4513.5,5020.5 cw(c4513.5,4967) 4567,4967 cw(c4513.5,4967) 4513.5,4913.5 4420.5,4913.5 ccw(c4420.5,4880) 4420.5,4846.5 4513.5,4846.5 cw(c4513.5,4793) 4567,4793 cw(c4513.5,4793) 4513.5,4739.5 4420.5,4739.5 ccw(c4420.5,4706) 4420.5,4672.5 4513.5,4672.5 cw(c4513.5,4619) 4567,4619 cw(c4513.5,4619) 4513.5,4565.5 4420.5,4565.5 ccw(c4420.5,4532) 4420.5,4498.5 4513.5,4498.5 cw(c4513.5,4445) 4567,4445 cw(c4513.5,4445) 4513.5,4391.5 4420.5,4391.5 ccw(c4420.5,4358) 4420.5,4324.5 4513.5,4324.5 cw(c4513.5,4271) 4567,4271 cw(c4513.5,4271) 4513.5,4217.5 4420.5,4217.5 ccw(c4420.5,4184) 4420.5,4150.5 4513.5,4150.5 cw(c4513.5,4097) 4567,4097 cw(c4513.5,4097) 4513.5,4043.5 4420.5,4043.5 ccw(c4420.5,4010) 4420.5,3976.5 4513.5,3976.5 cw(c4513.5,3923) 4567,3923 cw(c4513.5,3923) 4513.5,3869.5 4420.5,3869.5 ccw(c4420.5,3836) 4420.5,3802.5 4513.5,3802.5 cw(c4513.5,3749) 4567,3749 cw(c4513.5,3749) 4513.5,3695.5 4420.5,3695.5 ccw(c4420.5,3662) 4420.5,3628.5 4513.5,3628.5 cw(c4513.5,3575) 4567,3575 cw(c4513.5,3575) 4513.5,3521.5 4420.5,3521.5 ccw(c4420.5,3488) 4420.5,3454.5 4423.5,3454.5 cw(c4423.5,3401) 4477,3401 4477,3231 4579,3129 4579,3048
D13+: J303.4 U301.45 | length 2009
  Top Layer w8: 6345.74,3584.26 6381.32,3584.26 6391,3593.94 J303.4@6433,3593.94
  Top Layer w9: U301.45@4745.67,2870.87 4778.39,2870.87 4779.01,2871.49 4832.49,2871.49 4840.99,2880 4895,2880
  Top Layer w12: 4895,2880 4911.72,2880 4938.72,2907 5127.72,2907 5831.72,3611 6272.26,3611 6299,3584.26 6345.74,3584.26
D13-: J303.6 U301.44 | length 2007.7
  Top Layer w8: 6346.74,3564.26 6381.32,3564.26 6391,3554.57 J303.6@6433,3554.57
  Top Layer w9: U301.44@4745.67,2855.12 4778.39,2855.12 4779.01,2854.49 4836.01,2854.49 4839.53,2854.49 4845.04,2860 4896,2860
  Top Layer w12: 4895,2860 4920,2860 4947,2887 5136,2887 5840,3591 6263.97,3591 6290.72,3564.26 6345.74,3564.26
D21+: J301.1 U301.12 | length 2026
  Top Layer w8: J301.1@2730,3296 2762,3296 2771.68,3305.68 2803,3305.68 ; 4336,2678 4402.26,2744.26
  Top Layer w9: 4326,2678 4336,2678 ; 4402.26,2744.26 4420.99,2744.26 4421.61,2744.88 U301.12@4454.33,2744.88
  Top Layer w12: J301.1@2720,3296 J301.1@2730,3296 ; 2803,3305.68 2876.03,3305.68 3503.72,2678 4326,2678
D21-: J301.3 U301.11 | length 2024.8
  Top Layer w8: J301.3@2720,3335.37 2762,3335.37 2771.68,3325.69 2804,3325.69 ; 4335,2698 4398.26,2761.26
  Top Layer w9: 4326,2698 4335,2698 ; 4398.26,2761.26 4420.99,2761.26 4421.61,2760.63 U301.11@4454.33,2760.63
  Top Layer w12: 2804,3325.69 2884.31,3325.69 3512,2698 4326,2698
D22+: J302.1 U301.62 | length 6000.6
  Top Layer w8: J302.1@4460,5896 4460,5854 4469.68,5844.32 4469.68,5814
  Top Layer w9: 4486.36,3009.36 4512.76,2982.96 4512.76,2979.01 4513.39,2978.39 U301.62@4513.39,2945.67
  Top Layer w12: 4469.68,5814 4469.68,5800.97 4194,5525.28 4194,5227 ccw(c4247.5,5227) 4247.5,5173.5 4250.1,5173.5 cw(c4250.1,5140) 4283.6,5140 cw(c4250.1,5140) 4250.1,5106.5 4157.9,5106.5 ccw(c4157.9,5053) 4157.9,4999.5 4250.1,4999.5 cw(c4250.1,4966) 4283.6,4966 cw(c4250.1,4966) 4250.1,4932.5 4157.9,4932.5 ccw(c4157.9,4879) 4157.9,4825.5 4250.1,4825.5 cw(c4250.1,4792) 4283.6,4792 cw(c4250.1,4792) 4250.1,4758.5 4157.9,4758.5 ccw(c4157.9,4705) 4157.9,4651.5 4250.1,4651.5 cw(c4250.1,4618) 4283.6,4618 cw(c4250.1,4618) 4250.1,4584.5 4157.9,4584.5 ccw(c4157.9,4531) 4157.9,4477.5 4250.1,4477.5 cw(c4250.1,4444) 4283.6,4444 cw(c4250.1,4444) 4250.1,4410.5 4157.9,4410.5 ccw(c4157.9,4357) 4157.9,4303.5 4250.1,4303.5 cw(c4250.1,4270) 4283.6,4270 cw(c4250.1,4270) 4250.1,4236.5 4157.9,4236.5 ccw(c4157.9,4183) 4157.9,4129.5 4250.1,4129.5 cw(c4250.1,4096) 4283.6,4096 cw(c4250.1,4096) 4250.1,4062.5 4157.9,4062.5 ccw(c4157.9,4009) 4157.9,3955.5 4250.1,3955.5 cw(c4250.1,3922) 4283.6,3922 cw(c4250.1,3922) 4250.1,3888.5 4157.9,3888.5 ccw(c4157.9,3835) 4157.9,3781.5 4250.1,3781.5 cw(c4250.1,3748) 4283.6,3748 cw(c4250.1,3748) 4250.1,3714.5 4157.9,3714.5 ccw(c4157.9,3661) 4157.9,3607.5 4250.1,3607.5 cw(c4250.1,3574) 4283.6,3574 cw(c4250.1,3574) 4250.1,3540.5 4157.9,3540.5 ccw(c4157.9,3487) 4157.9,3433.5 4160.5,3433.5 cw(c4160.5,3400) 4194,3400 4194,3301.72 4486.36,3009.36
D22-: J302.3 U301.61 | length 5998.9
  Top Layer w8: 4489.69,5821 4489.69,5844.32 4499.37,5854 J302.3@4499.37,5896
  Top Layer w9: 4500.5,3023.5 4529.13,2994.87 U301.61@4529.13,2945.67
  Top Layer w12: 4489.69,5821 4489.69,5792.69 4214,5517 4214,5227 ccw(c4247.5,5227) 4247.5,5193.5 4250.1,5193.5 cw(c4250.1,5140) 4303.6,5140 cw(c4250.1,5140) 4250.1,5086.5 4157.9,5086.5 ccw(c4157.9,5053) 4157.9,5019.5 4250.1,5019.5 cw(c4250.1,4966) 4303.6,4966 cw(c4250.1,4966) 4250.1,4912.5 4157.9,4912.5 ccw(c4157.9,4879) 4157.9,4845.5 4250.1,4845.5 cw(c4250.1,4792) 4303.6,4792 cw(c4250.1,4792) 4250.1,4738.5 4157.9,4738.5 ccw(c4157.9,4705) 4157.9,4671.5 4250.1,4671.5 cw(c4250.1,4618) 4303.6,4618 cw(c4250.1,4618) 4250.1,4564.5 4157.9,4564.5 ccw(c4157.9,4531) 4157.9,4497.5 4250.1,4497.5 cw(c4250.1,4444) 4303.6,4444 cw(c4250.1,4444) 4250.1,4390.5 4157.9,4390.5 ccw(c4157.9,4357) 4157.9,4323.5 4250.1,4323.5 cw(c4250.1,4270) 4303.6,4270 cw(c4250.1,4270) 4250.1,4216.5 4157.9,4216.5 ccw(c4157.9,4183) 4157.9,4149.5 4250.1,4149.5 cw(c4250.1,4096) 4303.6,4096 cw(c4250.1,4096) 4250.1,4042.5 4157.9,4042.5 ccw(c4157.9,4009) 4157.9,3975.5 4250.1,3975.5 cw(c4250.1,3922) 4303.6,3922 cw(c4250.1,3922) 4250.1,3868.5 4157.9,3868.5 ccw(c4157.9,3835) 4157.9,3801.5 4250.1,3801.5 cw(c4250.1,3748) 4303.6,3748 cw(c4250.1,3748) 4250.1,3694.5 4157.9,3694.5 ccw(c4157.9,3661) 4157.9,3627.5 4250.1,3627.5 cw(c4250.1,3574) 4303.6,3574 cw(c4250.1,3574) 4250.1,3520.5 4157.9,3520.5 ccw(c4157.9,3487) 4157.9,3453.5 4160.5,3453.5 cw(c4160.5,3400) 4214,3400 4214,3310 4500.5,3023.5
D23+: J303.1 U301.48 | length 2025.4
  Top Layer w8: 6359.32,3643.32 6381.32,3643.32 6391,3653 J303.1@6433,3653
  Top Layer w9: U301.48@4745.67,2918.11 4778.39,2918.11 4779.01,2918.74 4785.69,2918.74 4805.96,2939 4825,2939
  Top Layer w12: 4825,2939 5570,3684 6299.28,3684 6339.97,3643.32 6359.32,3643.32
D23-: J303.3 U301.47 | length 2022.8
  Top Layer w8: 6360.69,3623.31 6381.32,3623.31 6391,3613.63 J303.3@6433,3613.63
  Top Layer w9: U301.47@4745.67,2902.36 4778.39,2902.36 4779.01,2901.74 4792.74,2901.74 4810,2919 4825,2919
  Top Layer w12: 4825,2919 4833,2919 5578,3664 6291,3664 6331.69,3623.31 6359.32,3623.31
D31+: J301.10 R360.1 U301.4 | length 2034.7
  Top Layer w8: J301.10@2720,3473.17 2762,3473.17 2771.68,3482.85 2794.85,3482.85
  Top Layer w9: 4326.5,2903.5 4337.5,2903.5 4370.76,2870.24 4420.99,2870.24 4421.61,2870.87 U301.4@4454.33,2870.87
  Top Layer w12: 2794.85,3482.85 2843.85,3482.85 2875,3514 3392.15,3514 ; 3392.15,3513.85 3439.83,3513.85 R360.1@3459,3494.68 3478.17,3513.85 ; 3477.46,3513.85 3716.15,3513.85 4326.5,2903.5
D31-: J301.12 R361.1 U301.3 | length 2033.9
  Top Layer w8: J301.12@2720,3512.54 2762,3512.54 2771.68,3502.85 2794.85,3502.85
  Top Layer w9: 4333.5,2925.5 4341.5,2925.5 4379.76,2887.24 4420.99,2887.24 4421.61,2886.61 U301.3@4454.33,2886.61
  Top Layer w12: 2794.85,3502.85 2835.57,3502.85 2866.72,3534 3400.43,3534 ; 3400.43,3533.85 3439.83,3533.85 ; 3440.54,3533.85 R361.1@3459,3552.32 3477.46,3533.85 3725.15,3533.85 4333.5,2925.5
D32+: J302.10 R358.1 U301.54 | length 6019
  Top Layer w8: J302.10@4637.17,5896 4637.17,5854 4646.85,5844.32 4646.85,5815
  Top Layer w9: U301.54@4639.37,2945.67 4639.37,2978.39 4638.74,2979.01 4638.74,2992.03 4676.86,3030.14
  Top Layer w12: 4646.85,5815 4646.85,5779.87 4916.92,5509.8 R358.1@4916.92,5472.92 4953.8,5472.92 5016,5410.72 5016,5228 ccw(c5069.5,5228) 5069.5,5174.5 ; 4676.86,3030.14 5016,3369.28 5016,3401 ccw(c4982.5,3401) 4982.5,3434.5 ; 4981.51,3434.5 cw(c4981.51,3488) 4981.51,3541.5 5070.49,3541.5 ccw(c5070.49,3575) 5103.99,3575 ccw(c5070.49,3575) 5070.49,3608.5 4981.51,3608.5 cw(c4981.51,3662) 4981.51,3715.5 5070.49,3715.5 ccw(c5070.49,3749) 5103.99,3749 ccw(c5070.49,3749) 5070.49,3782.5 4981.51,3782.5 cw(c4981.51,3836) 4981.51,3889.5 5070.49,3889.5 ccw(c5070.49,3923) 5103.99,3923 ccw(c5070.49,3923) 5070.49,3956.5 4981.51,3956.5 cw(c4981.51,4010) 4981.51,4063.5 5070.49,4063.5 ccw(c5070.49,4097) 5103.99,4097 ccw(c5070.49,4097) 5070.49,4130.5 4981.51,4130.5 cw(c4981.51,4184) 4981.51,4237.5 5070.49,4237.5 ccw(c5070.49,4271) 5103.99,4271 ccw(c5070.49,4271) 5070.49,4304.5 4981.51,4304.5 cw(c4981.51,4358) 4981.51,4411.5 5070.49,4411.5 ccw(c5070.49,4445) 5103.99,4445 ccw(c5070.49,4445) 5070.49,4478.5 4981.51,4478.5 cw(c4981.51,4532) 4981.51,4585.5 5070.49,4585.5 ccw(c5070.49,4619) 5103.99,4619 ccw(c5070.49,4619) 5070.49,4652.5 4981.51,4652.5 cw(c4981.51,4706) 4981.51,4759.5 5070.49,4759.5 ccw(c5070.49,4793) 5103.99,4793 ccw(c5070.49,4793) 5070.49,4826.5 4981.51,4826.5 cw(c4981.51,4880) 4981.51,4933.5 5070.49,4933.5 ccw(c5070.49,4967) 5103.99,4967 ccw(c5070.49,4967) 5070.49,5000.5 4981.51,5000.5 cw(c4981.51,5054) 4981.51,5107.5 5070.49,5107.5 ccw(c5070.49,5141) 5103.99,5141 ccw(c5070.49,5141) 5070.49,5174.5
D32-: J302.12 R359.1 U301.53 | length 6020.4
  Top Layer w8: 4666.85,5817 4666.85,5844.32 4676.54,5854 J302.12@4676.54,5896
  Top Layer w9: U301.53@4655.12,2945.67 4655.12,2978.39 4655.74,2979.01 4655.74,2980.74 4691,3016
  Top Layer w12: 4666.85,5817 4666.85,5788.15 4932.92,5522.08 R359.1@4970.08,5522.08 4970.08,5484.92 5036,5419 5036,5228 ccw(c5069.5,5228) 5069.5,5194.5 ; 4691,3016 5036,3361 5036,3401 ccw(c4982.5,3401) 4982.5,3454.5 ; 4981.51,3454.5 cw(c4981.51,3488) 4981.51,3521.5 5070.49,3521.5 ccw(c5070.49,3575) 5123.99,3575 ccw(c5070.49,3575) 5070.49,3628.5 4981.51,3628.5 cw(c4981.51,3662) 4981.51,3695.5 5070.49,3695.5 ccw(c5070.49,3749) 5123.99,3749 ccw(c5070.49,3749) 5070.49,3802.5 4981.51,3802.5 cw(c4981.51,3836) 4981.51,3869.5 5070.49,3869.5 ccw(c5070.49,3923) 5123.99,3923 ccw(c5070.49,3923) 5070.49,3976.5 4981.51,3976.5 cw(c4981.51,4010) 4981.51,4043.5 5070.49,4043.5 ccw(c5070.49,4097) 5123.99,4097 ccw(c5070.49,4097) 5070.49,4150.5 4981.51,4150.5 cw(c4981.51,4184) 4981.51,4217.5 5070.49,4217.5 ccw(c5070.49,4271) 5123.99,4271 ccw(c5070.49,4271) 5070.49,4324.5 4981.51,4324.5 cw(c4981.51,4358) 4981.51,4391.5 5070.49,4391.5 ccw(c5070.49,4445) 5123.99,4445 ccw(c5070.49,4445) 5070.49,4498.5 4981.51,4498.5 cw(c4981.51,4532) 4981.51,4565.5 5070.49,4565.5 ccw(c5070.49,4619) 5123.99,4619 ccw(c5070.49,4619) 5070.49,4672.5 4981.51,4672.5 cw(c4981.51,4706) 4981.51,4739.5 5070.49,4739.5 ccw(c5070.49,4793) 5123.99,4793 ccw(c5070.49,4793) 5070.49,4846.5 4981.51,4846.5 cw(c4981.51,4880) 4981.51,4913.5 5070.49,4913.5 ccw(c5070.49,4967) 5123.99,4967 ccw(c5070.49,4967) 5070.49,5020.5 4981.51,5020.5 cw(c4981.51,5054) 4981.51,5087.5 5070.49,5087.5 ccw(c5070.49,5141) 5123.99,5141 ccw(c5070.49,5141) 5070.49,5194.5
